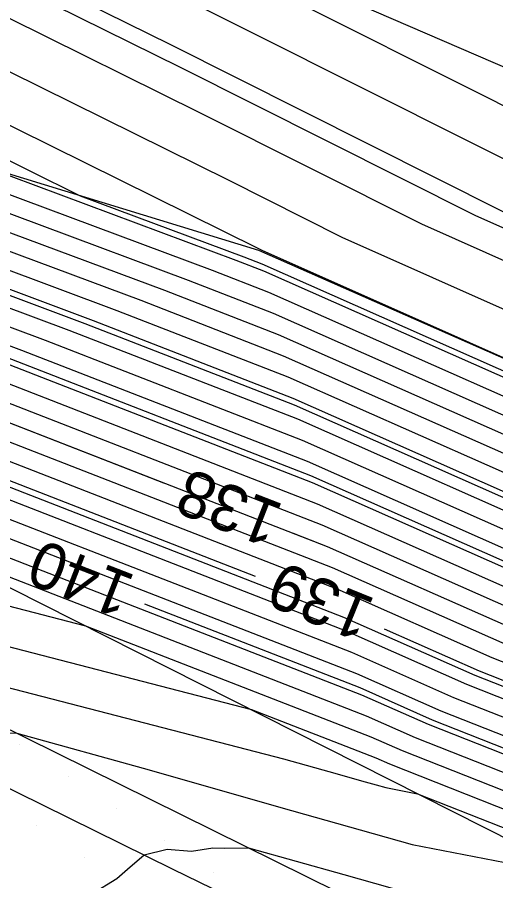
# Model space of a CAD drawing. Extents: x 2354170 to 2357230, y 866100 to 868290.
# Drawn here: x 2355058.23 to 2355078.86, y 867535.31 to 867572.53 of the extents above; entities that cross this region are included whole.
import ezdxf

# ---------------------------------------------------------------- set-up
doc = ezdxf.new("R2010")
doc.units = 0
for name, color, linetype in [('Default', 7, 'Continuous'), ('DTM Contours Major', 7, 'Continuous'), ('DTM Contours Major Text', 7, 'Continuous'), ('DTM Contours Minor', 7, 'Continuous'), ('Exist DTM Breakline', 7, 'Continuous'), ('Exist DTM Scan Elevation Point', 7, 'Continuous'), ('Exist Roads EOP', 7, 'Continuous'), ('PH Exist DTM Breakline', 7, 'Continuous')]:
    doc.layers.add(name, color=color, linetype=linetype)

msp = doc.modelspace()

# ---------------------------------------------------------------- linework, layer by layer
at = {"layer": 'Default'}
for points in [[(2354972.811, 867592.054), (2354993.379, 867583.613), (2354998.147, 867581.297), (2355017.365, 867573.955), (2355023.646, 867571.223), (2355023.864, 867571.138), (2355039.001, 867563.761), (2355049.388, 867558.274), (2355054.316, 867556.436), (2355064.534, 867552.462)], [(2355003.273, 867589.958), (2355012.346, 867585.508), (2355014.512, 867584.62), (2355028.775, 867578.417), (2355032.927, 867575.623), (2355052.64, 867565.209), (2355064.575, 867560.758), (2355069.477, 867558.851), (2355085.298, 867551.851), (2355086.723, 867551.29), (2355093.921, 867548.105)], [(2355079.464, 867548.694), (2355070.954, 867552.459), (2355057.393, 867557.732), (2355050.364, 867560.354), (2355035.545, 867568.183), (2355025.252, 867573.199), (2355025.104, 867573.257), (2355015.865, 867577.275), (2355002.797, 867582.268), (2354992.964, 867587.044), (2354988.082, 867589.048)], [(2354999.161, 867588.34), (2355008.997, 867583.562), (2355013.864, 867581.702), (2355027.048, 867575.968), (2355027.103, 867575.947), (2355030.937, 867574.078), (2355051.664, 867563.128), (2355061.497, 867559.461), (2355070.11, 867556.112), (2355083.646, 867550.122), (2355086.139, 867549.14), (2355090.249, 867547.322)], [(2354975.638, 867584.852), (2354976.793, 867584.58), (2354992.187, 867580.363), (2354993.065, 867580.122), (2354993.602, 867579.987), (2354993.946, 867579.903), (2354994.183, 867579.846), (2354995.101, 867579.713), (2355018.865, 867570.634), (2355022.188, 867569.189), (2355022.475, 867569.077), (2355042.456, 867559.34), (2355048.413, 867556.193), (2355051.238, 867555.139), (2355068.491, 867548.43)], [(2355039.748, 867582.774), (2355057.845, 867572.501), (2355066.09, 867568.423), (2355075.66, 867563.616), (2355088.2, 867558.035), (2355090.288, 867556.998), (2355109.078, 867548.638), (2355117.687, 867544.873), (2355118.143, 867544.673), (2355135.4, 867537.032), (2355142.924, 867534.128), (2355152.971, 867529.837), (2355153.53, 867529.622), (2355160.154, 867526.024), (2355180.934, 867517.127), (2355182.414, 867516.349), (2355190.855, 867512.84), (2355199.936, 867509.264)], [(2355030.605, 867581.098), (2355048.031, 867569.375), (2355053.29, 867566.596), (2355066.627, 867561.622), (2355069.054, 867560.678), (2355086.4, 867553.004), (2355087.112, 867552.723), (2355112.383, 867541.543), (2355114.567, 867540.679), (2355114.963, 867540.522), (2355137.014, 867531.279), (2355139.122, 867530.678), (2355151.331, 867525.417), (2355153.823, 867524.387), (2355178.286, 867513.844), (2355180.51, 867512.86), (2355190.971, 867508.066), (2355192.601, 867507.384), (2355218.305, 867495.571)], [(2354995.047, 867580.65), (2355018.365, 867571.741), (2355022.674, 867569.867), (2355022.938, 867569.764), (2355041.304, 867560.814), (2355048.738, 867556.887), (2355052.264, 867555.571), (2355072.009, 867547.892), (2355078.691, 867544.936), (2355084.387, 867542.691), (2355094.899, 867538.04), (2355111.939, 867531.298), (2355115.029, 867530.075), (2355125.868, 867525.532), (2355139.851, 867521.546), (2355141.602, 867520.791), (2355158.318, 867513.884), (2355164.901, 867511.046), (2355180.153, 867504.304), (2355183.645, 867502.704), (2355196.955, 867497.127)], [(2355047.68, 867580.67), (2355059.165, 867574.151), (2355064.839, 867571.345), (2355079.106, 867564.179), (2355088.55, 867559.976), (2355091.682, 867558.42), (2355106.052, 867552.026), (2355119.095, 867546.322), (2355119.785, 867546.02), (2355133.029, 867540.156), (2355138.125, 867538.189)], [(2355029.69, 867579.758), (2355040.479, 867572.499), (2355052.965, 867565.903), (2355065.601, 867561.19), (2355069.265, 867559.765), (2355085.849, 867552.427), (2355086.917, 867552.006), (2355111.135, 867541.292), (2355114.379, 867540.009), (2355114.968, 867539.776), (2355136.218, 867530.869), (2355139.174, 867530.026), (2355150.636, 867525.087), (2355154.144, 867523.637), (2355177.33, 867513.644), (2355180.485, 867512.249), (2355190.448, 867507.683), (2355192.912, 867506.651), (2355217.532, 867495.337)], [(2355036.147, 867579.326), (2355052.38, 867568.405), (2355053.886, 867567.55), (2355056.858, 867566.08), (2355067.652, 867562.054), (2355068.843, 867561.591), (2355086.95, 867553.58), (2355087.307, 867553.439), (2355113.632, 867541.793), (2355114.755, 867541.349), (2355114.958, 867541.268), (2355126.204, 867536.555)], [(2355043.958, 867577.984), (2355056.525, 867570.85), (2355067.342, 867565.501), (2355072.214, 867563.054), (2355087.851, 867556.095), (2355088.894, 867555.577), (2355112.103, 867545.25), (2355116.28, 867543.423), (2355116.501, 867543.327), (2355137.772, 867533.908), (2355140.329, 867532.921), (2355153.012, 867527.504), (2355153.21, 867527.428), (2355155.552, 867526.156), (2355180.709, 867515.384), (2355181.269, 867515.089), (2355191.411, 867510.874), (2355196.056, 867509.044)], [(2355028.633, 867577.026), (2355052.315, 867564.516), (2355063.549, 867560.326), (2355069.688, 867557.938), (2355084.748, 867551.275), (2355086.528, 867550.573), (2355108.637, 867540.792), (2355114.004, 867538.669), (2355114.977, 867538.283), (2355134.626, 867530.048), (2355139.278, 867528.721), (2355149.246, 867524.426), (2355154.786, 867522.137), (2355175.418, 867513.244), (2355180.434, 867511.027), (2355189.401, 867506.917), (2355193.534, 867505.186)], [(2355062.336, 867577.188), (2355085.998, 867565.304), (2355089.249, 867563.857), (2355094.47, 867561.263), (2355100.002, 867558.802), (2355121.91, 867549.221), (2355123.07, 867548.714), (2355128.285, 867546.405), (2355150.708, 867537.749), (2355152.846, 867536.836), (2355154.489, 867536.205), (2355173.961, 867525.629), (2355181.609, 867522.355), (2355185.848, 867520.129), (2355189.188, 867518.74), (2355211.575, 867509.924)], [(2355002.655, 867575.912), (2355019.366, 867569.527), (2355021.702, 867568.511), (2355022.012, 867568.39), (2355043.608, 867557.866), (2355048.087, 867555.5), (2355050.212, 867554.707), (2355072.431, 867546.066), (2355077.59, 867543.784), (2355083.997, 867541.258), (2355092.402, 867537.54), (2355111.563, 867529.958), (2355115.038, 867528.583), (2355124.276, 867524.711), (2355139.955, 867520.242), (2355140.213, 867520.131), (2355158.96, 867512.383), (2355162.989, 867510.647), (2355180.102, 867503.082), (2355182.598, 867501.938), (2355197.577, 867495.662)], [(2355029.785, 867575.552), (2355051.989, 867563.822), (2355062.523, 867559.893), (2355069.899, 867557.025), (2355084.197, 867550.699), (2355086.333, 867549.857), (2355107.388, 867540.542), (2355113.816, 867537.999), (2355114.982, 867537.537), (2355133.83, 867529.637), (2355139.331, 867528.069), (2355148.551, 867524.095), (2355155.107, 867521.386), (2355174.462, 867513.045), (2355180.408, 867510.416), (2355188.878, 867506.534), (2355193.845, 867504.453)], [(2355196.022, 867499.325), (2355185.215, 867503.853), (2355180.229, 867506.138), (2355167.77, 867511.646), (2355157.355, 867516.135), (2355143.687, 867521.783), (2355139.695, 867523.503), (2355128.257, 867526.764), (2355115.015, 867532.314), (2355112.502, 867533.308), (2355098.646, 867538.791), (2355084.971, 867544.841), (2355080.343, 867546.665), (2355071.376, 867550.632), (2355055.342, 867556.868), (2355049.713, 867558.967), (2355037.849, 867565.235), (2355024.326, 867571.825), (2355024.132, 867571.901), (2355016.865, 867575.061)], [(2355194.778, 867502.255), (2355187.308, 867505.385), (2355180.331, 867508.582), (2355171.594, 867512.445), (2355156.07, 867519.136), (2355146.466, 867523.104), (2355139.487, 867526.112), (2355131.441, 867528.406), (2355114.996, 867535.299), (2355113.253, 867535.988), (2355103.641, 867539.791), (2355085.749, 867547.707), (2355082.545, 867548.97), (2355070.532, 867554.285), (2355059.445, 867558.597), (2355051.014, 867561.741), (2355033.241, 867571.131), (2355026.177, 867574.573)], [(2355063.587, 867574.266), (2355082.552, 867564.741), (2355088.899, 867561.917), (2355093.076, 867559.842), (2355103.027, 867555.414), (2355120.503, 867547.772), (2355121.428, 867547.367), (2355130.657, 867543.28), (2355148.114, 867536.542), (2355152.888, 867534.503), (2355154.169, 867534.011), (2355169.359, 867525.761), (2355181.384, 867520.612), (2355184.703, 867518.869), (2355189.744, 867516.774), (2355207.695, 867509.704)], [(2354998.866, 867573.748), (2355010.208, 867572.11), (2355019.866, 867568.42), (2355021.216, 867567.833), (2355021.55, 867567.703), (2355044.76, 867556.392), (2355047.762, 867554.806), (2355049.186, 867554.275), (2355072.643, 867545.153), (2355077.039, 867543.207), (2355083.803, 867540.541), (2355091.153, 867537.289), (2355111.376, 867529.288), (2355115.043, 867527.837), (2355123.48, 867524.301), (2355138.516, 867520.014), (2355140.061, 867519.404), (2355144.636, 867517.685), (2355159.281, 867511.633), (2355162.033, 867510.447), (2355180.076, 867502.471), (2355182.075, 867501.555), (2355197.888, 867494.929)], [(2355195.089, 867501.523), (2355186.785, 867505.002), (2355180.306, 867507.971), (2355170.638, 867512.245), (2355156.392, 867518.385), (2355145.772, 867522.774), (2355139.539, 867525.46), (2355130.645, 867527.995), (2355115.001, 867534.553), (2355113.065, 867535.318), (2355102.393, 867539.541), (2355085.555, 867546.99), (2355081.995, 867548.394), (2355070.743, 867553.372), (2355058.419, 867558.165), (2355050.689, 867561.048), (2355034.393, 867569.657), (2355025.715, 867573.886)], [(2355048.169, 867573.195), (2355055.206, 867569.2), (2355068.594, 867562.579), (2355068.769, 867562.491), (2355086.8, 867554.466), (2355087.501, 867554.156), (2355087.501, 867554.156), (2355114.881, 867542.043), (2355114.942, 867542.019), (2355114.954, 867542.014), (2355138.607, 867532.1), (2355139.018, 867531.983), (2355152.72, 867526.078), (2355153.181, 867525.888), (2355180.198, 867514.243), (2355180.561, 867514.083), (2355190.76, 867509.409), (2355191.967, 867508.907), (2355192.176, 867508.825), (2355218.458, 867497.985)], [(2355017.865, 867572.848), (2355023.16, 867570.545), (2355023.401, 867570.451), (2355040.152, 867562.287), (2355049.063, 867557.58), (2355053.29, 867556.004), (2355071.798, 867548.806), (2355079.242, 867545.512), (2355084.581, 867543.407), (2355096.148, 867538.29), (2355112.126, 867531.968), (2355115.024, 867530.822), (2355126.665, 867525.943), (2355139.799, 867522.198), (2355142.297, 867521.122), (2355157.997, 867514.634), (2355165.857, 867511.246), (2355180.178, 867504.915), (2355184.168, 867503.087), (2355196.644, 867497.86)], [(2355195.711, 867500.057), (2355185.738, 867504.236), (2355180.255, 867506.749), (2355168.726, 867511.846), (2355157.034, 867516.885), (2355144.382, 867522.113), (2355139.643, 867524.155), (2355129.053, 867527.174), (2355115.01, 867533.06), (2355112.69, 867533.978), (2355099.895, 867539.041), (2355085.165, 867545.557), (2355080.893, 867547.241), (2355071.165, 867551.545), (2355056.368, 867557.3), (2355050.038, 867559.661), (2355036.697, 867566.709), (2355024.789, 867572.512), (2355024.618, 867572.579)], [(2355194.467, 867502.988), (2355187.831, 867505.768), (2355180.357, 867509.194), (2355172.55, 867512.645), (2355155.749, 867519.886), (2355147.161, 867523.435), (2355139.435, 867526.765), (2355132.238, 867528.816), (2355114.991, 867536.045), (2355113.441, 867536.658), (2355104.89, 867540.042), (2355085.944, 867548.423), (2355083.096, 867549.546), (2355070.321, 867555.198), (2355060.471, 867559.029), (2355051.339, 867562.435), (2355032.089, 867572.605)], [(2355001.207, 867570.699), (2355017.762, 867568.308), (2355020.366, 867567.313), (2355020.73, 867567.155), (2355021.087, 867567.016), (2355045.912, 867554.918), (2355047.437, 867554.112), (2355048.16, 867553.843), (2355072.854, 867544.239), (2355076.489, 867542.631), (2355083.608, 867539.825), (2355089.904, 867537.039), (2355111.188, 867528.618), (2355115.048, 867527.091), (2355122.684, 867523.89), (2355136.293, 867520.011), (2355140.195, 867518.469), (2355151.754, 867514.126), (2355159.602, 867510.883), (2355161.077, 867510.247), (2355180.05, 867501.86), (2355181.552, 867501.172), (2355198.199, 867494.196)], [(2355008.062, 867566.52), (2355016.247, 867565.337), (2355019.691, 867564.85), (2355019.951, 867564.834), (2355021.645, 867564.557), (2355022.676, 867564.401), (2355045.733, 867554.093), (2355047.064, 867553.444), (2355047.112, 867553.419), (2355047.134, 867553.411), (2355073.065, 867543.326), (2355075.938, 867542.055), (2355079.698, 867540.573)], [(2355010.575, 867557.781), (2355012.369, 867558.87), (2355012.924, 867559.225), (2355013.245, 867559.533), (2355014.554, 867560.729), (2355014.927, 867560.821), (2355016.553, 867561.295), (2355017.821, 867561.664), (2355018.328, 867561.592), (2355018.339, 867561.591), (2355022.926, 867560.841), (2355025.72, 867560.419), (2355038.564, 867554.677), (2355042.342, 867553.414), (2355044.813, 867552.581), (2355046.573, 867551.972), (2355047.908, 867551.526), (2355048.904, 867551.226), (2355054.025, 867549.899), (2355073.276, 867542.413), (2355075.387, 867541.479), (2355083.219, 867538.391)], [(2355083.024, 867537.675), (2355074.837, 867540.902), (2355073.487, 867541.5), (2355061.18, 867546.286), (2355050.767, 867548.983), (2355048.742, 867549.592), (2355046.027, 867550.499), (2355042.448, 867551.737), (2355037.424, 867553.433), (2355029.742, 867555.999)], [(2355082.829, 867536.958), (2355074.286, 867540.326), (2355073.698, 867540.586), (2355068.335, 867542.672), (2355052.63, 867546.74), (2355049.575, 867547.659), (2355045.481, 867549.027), (2355040.083, 867550.894), (2355038.38, 867551.469), (2355035.539, 867550.873), (2355034.87, 867550.717)], [(2355070.126, 867550.287), (2355071.587, 867549.719), (2355079.792, 867546.089), (2355084.776, 867544.124), (2355097.397, 867538.54), (2355112.314, 867532.638), (2355115.02, 867531.568), (2355127.461, 867526.353), (2355139.747, 867522.851), (2355142.992, 867521.452), (2355157.676, 867515.384), (2355162.877, 867513.143)], [(2355074.048, 867546.171), (2355078.14, 867544.36), (2355084.192, 867541.974), (2355093.651, 867537.79), (2355111.751, 867530.628), (2355115.034, 867529.329), (2355125.072, 867525.122), (2355139.903, 867520.894), (2355140.907, 867520.461), (2355158.639, 867513.134), (2355163.945, 867510.847), (2355166.979, 867509.506)], [(2355054.493, 867544.497), (2355069.706, 867540.557), (2355072.016, 867539.919), (2355073.07, 867539.618), (2355073.702, 867539.441), (2355074.118, 867539.324), (2355075.489, 867539.058), (2355082.635, 867536.242)], [(2355044.671, 867535.223), (2355045.066, 867535.461), (2355045.735, 867535.718), (2355046.732, 867536.142), (2355047.34, 867536.455), (2355048.633, 867537.391), (2355049.484, 867538.034), (2355050.571, 867538.496), (2355052.233, 867539.213), (2355053.654, 867540.469), (2355054.185, 867540.98), (2355054.322, 867541.032), (2355055.937, 867541.31), (2355057.579, 867541.678), (2355058.208, 867541.661), (2355063.913, 867540.088), (2355069.597, 867538.462), (2355073.005, 867537.506), (2355075.248, 867536.875), (2355082.374, 867535.497)], [(2355061.449, 867534.744), (2355062.526, 867535.401), (2355062.982, 867535.813), (2355063.695, 867536.42), (2355064.696, 867536.662), (2355065.735, 867536.587), (2355066.666, 867536.729), (2355067.165, 867536.713), (2355068.202, 867536.723), (2355072.307, 867535.571), (2355076.377, 867534.425)]]:
    msp.add_lwpolyline(points, dxfattribs=at)
at = {"layer": 'DTM Contours Major'}
for points in [[(2355003.273, 867589.958), (2355012.346, 867585.508), (2355014.512, 867584.62), (2355028.775, 867578.417), (2355032.927, 867575.623), (2355052.64, 867565.209), (2355064.575, 867560.758), (2355069.477, 867558.851), (2355085.298, 867551.851), (2355086.723, 867551.29), (2355093.921, 867548.105)], [(2355063.712, 867547.241), (2355072.994, 867543.631), (2355076.122, 867542.247), (2355083.478, 867539.347), (2355089.071, 867536.872), (2355111.063, 867528.171), (2355115.051, 867526.593), (2355122.153, 867523.616), (2355134.81, 867520.008), (2355140.285, 867517.846), (2355156.499, 867511.754), (2355157.043, 867511.529)]]:
    msp.add_lwpolyline(points, dxfattribs=at)
at = {"layer": 'DTM Contours Minor'}
for points in [[(2355123.364, 867530.551), (2355115.004, 867534.055), (2355112.94, 867534.872), (2355101.56, 867539.374), (2355085.425, 867546.513), (2355081.628, 867548.01), (2355070.884, 867552.763), (2355057.735, 867557.876), (2355050.472, 867560.586), (2355035.161, 867568.674), (2355025.406, 867573.428), (2355025.266, 867573.483), (2355015.698, 867577.644), (2355003.313, 867582.376), (2354992.918, 867587.426), (2354978.558, 867593.319), (2354971.311, 867596.824), (2354965.917, 867600.499), (2354963.684, 867602.037), (2354958.662, 867605.619), (2354957.494, 867605.876), (2354953.523, 867608.055)], [(2355031.826, 867582.886), (2355050.977, 867570.001), (2355054.326, 867568.1), (2355060.938, 867564.83), (2355067.994, 867562.198), (2355068.773, 867561.896), (2355087.134, 867553.772), (2355087.371, 867553.678), (2355105.72, 867545.561)], [(2354998.582, 867581.131), (2355017.365, 867573.955), (2355023.646, 867571.223), (2355023.864, 867571.138), (2355039.001, 867563.761), (2355049.388, 867558.274), (2355054.316, 867556.436), (2355071.587, 867549.719), (2355079.792, 867546.089), (2355084.776, 867544.124), (2355097.397, 867538.54), (2355112.314, 867532.638), (2355115.02, 867531.568), (2355127.461, 867526.353), (2355139.747, 867522.851), (2355142.992, 867521.452), (2355157.676, 867515.384), (2355166.814, 867511.446), (2355180.204, 867505.527), (2355182.997, 867504.246)], [(2355124.882, 867532.395), (2355114.988, 867536.542), (2355113.566, 867537.105), (2355105.723, 867540.208), (2355086.074, 867548.901), (2355083.463, 867549.93), (2355070.18, 867555.807), (2355061.155, 867559.317), (2355051.556, 867562.897), (2355031.321, 867573.587)], [(2355058.725, 867573.601), (2355065.256, 867570.371), (2355077.958, 867563.991), (2355088.433, 867559.329), (2355091.217, 867557.946), (2355107.061, 867550.897), (2355110.094, 867549.57)], [(2355025.557, 867567.271), (2355042.84, 867558.848), (2355048.304, 867555.962), (2355050.896, 867554.995), (2355072.291, 867546.675), (2355077.957, 867544.168), (2355084.127, 867541.735), (2355093.234, 867537.706), (2355111.688, 867530.405), (2355115.035, 867529.081), (2355124.807, 867524.985), (2355139.92, 867520.676), (2355140.676, 867520.351), (2355158.746, 867512.884), (2355163.627, 867510.78), (2355180.119, 867503.489), (2355182.947, 867502.193), (2355197.37, 867496.15), (2355206.448, 867491.978), (2355210.008, 867490.464)], [(2355082.829, 867536.958), (2355074.286, 867540.326), (2355073.698, 867540.586), (2355068.335, 867542.672), (2355052.63, 867546.74), (2355049.575, 867547.659), (2355045.481, 867549.027), (2355040.083, 867550.894), (2355038.38, 867551.469), (2355035.539, 867550.873), (2355034.87, 867550.717)]]:
    msp.add_lwpolyline(points, dxfattribs=at)
at = {"layer": 'Exist DTM Breakline'}
msp.add_lwpolyline([(2355033.578, 867551.356), (2355035.819, 867550.248), (2355038.056, 867549.132), (2355040.293, 867548.015), (2355042.529, 867546.898), (2355044.766, 867545.781), (2355047.004, 867544.667), (2355049.243, 867543.555), (2355051.481, 867542.442), (2355053.72, 867541.329), (2355055.963, 867540.224), (2355058.206, 867539.12), (2355060.449, 867538.016), (2355062.692, 867536.912), (2355064.936, 867535.811), (2355067.181, 867534.712)], dxfattribs=at)
at = {"layer": 'Exist DTM Scan Elevation Point'}
for p, q in [((2355058.336, 867541.171), (2355058.336, 867541.171)), ((2355060.421, 867539.791), (2355060.421, 867539.791)), ((2355062.506, 867538.412), (2355062.506, 867538.412)), ((2355059.041, 867537.706), (2355059.041, 867537.706)), ((2355064.591, 867537.032), (2355064.591, 867537.032)), ((2355061.126, 867536.327), (2355061.126, 867536.327)), ((2355066.676, 867535.653), (2355066.676, 867535.653))]:
    msp.add_line(p, q, dxfattribs=at)
at = {"layer": 'Exist Roads EOP'}
msp.add_lwpolyline([(2355007.522, 867566.789), (2355012.893, 867564.114), (2355018.265, 867561.443), (2355023.639, 867558.774), (2355029.014, 867556.108), (2355034.391, 867553.444), (2355039.767, 867550.782), (2355045.145, 867548.12), (2355050.523, 867545.46), (2355055.902, 867542.801), (2355061.281, 867540.143), (2355066.66, 867537.485), (2355072.039, 867534.827), (2355077.418, 867532.169), (2355082.796, 867529.509)], dxfattribs=at)
at = {"layer": 'PH Exist DTM Breakline'}
for points in [[(2355035.245, 867587.895), (2355062.077, 867577.792), (2355096.215, 867563.043), (2355125.204, 867550.464), (2355154.737, 867537.91), (2355188.097, 867522.603), (2355227.663, 867504.53)], [(2355219.015, 867495.786), (2355180.571, 867514.321), (2355138.993, 867532.299), (2355114.953, 867542.057), (2355068.64, 867562.47), (2355053.527, 867567.101), (2355028.202, 867577.578)], [(2355020.895, 867566.731), (2355047.101, 867553.397), (2355082.445, 867535.545), (2355115.093, 867519.976), (2355148.878, 867503.069), (2355189.51, 867482.704), (2355236.497, 867458.891), (2355265.87, 867444.934), (2355289.255, 867433.719), (2355311.059, 867425.353), (2355318.523, 867424.7), (2355331.045, 867424.483), (2355346.844, 867422.718), (2355351.323, 867421.656), (2355352.941, 867418.753), (2355356.257, 867418.279), (2355358.394, 867419.067), (2355358.413, 867422.341), (2355356.281, 867425.567), (2355354.45, 867428.091), (2355352.258, 867431.151), (2355351.487, 867427.072), (2355351.536, 867425.452)]]:
    msp.add_lwpolyline(points, dxfattribs=at)

# ---------------------------------------------------------------- texts
at = {"layer": 'Default'}
for s, rotation, p in [('138', 158.7486, (2355069.784, 867551.493)), ('139', 157.8777, (2355073.742, 867547.423))]:
    msp.add_text(s, height=2, rotation=rotation, dxfattribs=at).set_placement(p)
at = {"layer": 'DTM Contours Major Text'}
msp.add_text('140', height=2, rotation=158.7486, dxfattribs=at).set_placement((2355063.399, 867548.435))

doc.saveas('drawing.dxf')
